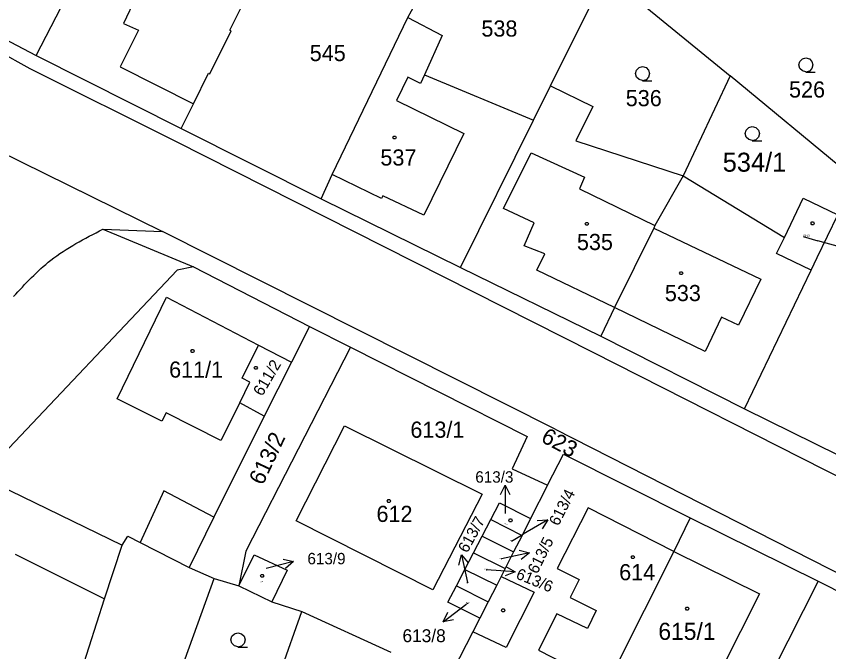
# Model space of a CAD drawing. Extents: x -621797 to -620972, y -1175539 to -1174697.
# Drawn here: x -621614.9 to -621529.4, y -1174912.8 to -1174845.9 of the extents above; entities that cross this region are included whole.
import ezdxf

# ---------------------------------------------------------------- set-up
doc = ezdxf.new("R2010")
doc.units = 0
for name, color, linetype in [('INZ mimo EON - nadz', 7, 'Continuous'), ('Rozvod plynu EON', 7, 'Continuous'), ('SDEL EON', 7, 'Continuous'), ('SDEL EON - popis', 7, 'Continuous'), ('Silnoproud EON', 7, 'Continuous'), ('Silnoproud EON - popis', 7, 'Continuous')]:
    doc.layers.add(name, color=color, linetype=linetype)

msp = doc.modelspace()

# ---------------------------------------------------------------- linework, layer by layer
at = {"layer": 'INZ mimo EON - nadz'}
for p, q in [((-621532.08, -1174869.11), (-621530.51, -1174869.55)), ((-621527.621, -1174870.36), (-621530.51, -1174869.55)), ((-621563.45, -1174895.28), (-621563.45, -1174898.28)), ((-621558.954, -1174898.939), (-621561.54, -1174900.46)), ((-621562.77, -1174901.18), (-621561.54, -1174900.46)), ((-621568.063, -1174902.62), (-621567.42, -1174905.55)), ((-621560.897, -1174902.42), (-621563.83, -1174903.05)), ((-621585.729, -1174903.343), (-621588.64, -1174904.07)), ((-621563.87, -1174903.06), (-621563.83, -1174903.05)), ((-621565.47, -1174904.2), (-621565.4, -1174904.21)), ((-621562.407, -1174904.418), (-621565.4, -1174904.21)), ((-621567.41, -1174905.6), (-621567.42, -1174905.55)), ((-621569.979, -1174909.672), (-621567.58, -1174907.87)), ((-621567.36, -1174907.71), (-621567.58, -1174907.87))]:
    msp.add_line(p, q, dxfattribs=at)
for points in [[(-621563.95, -1174896.28), (-621563.45, -1174895.28), (-621562.95, -1174896.28)], [(-621560.069, -1174899.015), (-621558.954, -1174898.939), (-621559.563, -1174899.877)], [(-621568.337, -1174903.704), (-621568.063, -1174902.62), (-621567.36, -1174903.489)], [(-621561.98, -1174902.141), (-621560.897, -1174902.42), (-621561.77, -1174903.119)], [(-621586.821, -1174903.101), (-621585.729, -1174903.343), (-621586.578, -1174904.071)], [(-621563.37, -1174903.85), (-621562.407, -1174904.418), (-621563.439, -1174904.847)], [(-621568.879, -1174909.471), (-621569.979, -1174909.672), (-621569.479, -1174908.671)]]:
    msp.add_lwpolyline(points, dxfattribs=at)
at = {"layer": 'Rozvod plynu EON'}
for points in [[(-621575.01, -1174858.53), (-621574.92, -1174858.68), (-621575.01, -1174858.83), (-621575.19, -1174858.83), (-621575.28, -1174858.68), (-621575.19, -1174858.53)], [(-621554.76, -1174867.62), (-621554.67, -1174867.77), (-621554.76, -1174867.92), (-621554.94, -1174867.92), (-621555.03, -1174867.77), (-621554.94, -1174867.62)], [(-621530.98, -1174867.56), (-621530.89, -1174867.71), (-621530.98, -1174867.86), (-621531.16, -1174867.86), (-621531.25, -1174867.71), (-621531.16, -1174867.56)], [(-621544.82, -1174872.82), (-621544.73, -1174872.97), (-621544.82, -1174873.12), (-621545, -1174873.12), (-621545.09, -1174872.97), (-621545, -1174872.82)], [(-621596.28, -1174881.02), (-621596.19, -1174881.17), (-621596.28, -1174881.32), (-621596.46, -1174881.32), (-621596.55, -1174881.17), (-621596.46, -1174881.02)], [(-621589.63, -1174882.79), (-621589.54, -1174882.94), (-621589.63, -1174883.09), (-621589.81, -1174883.09), (-621589.9, -1174882.94), (-621589.81, -1174882.79)], [(-621575.61, -1174896.82), (-621575.52, -1174896.97), (-621575.61, -1174897.12), (-621575.79, -1174897.12), (-621575.88, -1174896.97), (-621575.79, -1174896.82)], [(-621562.8, -1174898.84), (-621562.71, -1174898.99), (-621562.8, -1174899.14), (-621562.98, -1174899.14), (-621563.07, -1174898.99), (-621562.98, -1174898.84)], [(-621549.91, -1174902.73), (-621549.82, -1174902.88), (-621549.91, -1174903.03), (-621550.09, -1174903.03), (-621550.18, -1174902.88), (-621550.09, -1174902.73)], [(-621588.96, -1174904.7), (-621588.87, -1174904.85), (-621588.96, -1174905), (-621589.14, -1174905), (-621589.23, -1174904.85), (-621589.14, -1174904.7)], [(-621563.57, -1174908.33), (-621563.48, -1174908.48), (-621563.57, -1174908.63), (-621563.75, -1174908.63), (-621563.84, -1174908.48), (-621563.75, -1174908.33)], [(-621544.18, -1174908.15), (-621544.09, -1174908.3), (-621544.18, -1174908.45), (-621544.36, -1174908.45), (-621544.45, -1174908.3), (-621544.36, -1174908.15)]]:
    msp.add_lwpolyline(points, close=True, dxfattribs=at)
at = {"layer": 'SDEL EON'}
for points in [[(-621531.77, -1174851.77), (-621532.15, -1174851.67), (-621532.42, -1174851.4), (-621532.52, -1174851.03), (-621532.42, -1174850.66), (-621532.15, -1174850.39), (-621531.78, -1174850.29), (-621531.41, -1174850.39), (-621531.14, -1174850.66), (-621531.04, -1174851.04), (-621531.14, -1174851.42), (-621531.41, -1174851.69), (-621531.79, -1174851.79), (-621530.79, -1174851.79)], [(-621548.97, -1174852.68), (-621549.35, -1174852.58), (-621549.62, -1174852.31), (-621549.72, -1174851.94), (-621549.62, -1174851.57), (-621549.35, -1174851.3), (-621548.98, -1174851.2), (-621548.61, -1174851.3), (-621548.34, -1174851.57), (-621548.24, -1174851.95), (-621548.34, -1174852.33), (-621548.61, -1174852.6), (-621548.99, -1174852.7), (-621547.99, -1174852.7)], [(-621537.41, -1174859), (-621537.79, -1174858.9), (-621538.06, -1174858.63), (-621538.16, -1174858.26), (-621538.06, -1174857.89), (-621537.79, -1174857.62), (-621537.42, -1174857.52), (-621537.05, -1174857.62), (-621536.78, -1174857.89), (-621536.68, -1174858.27), (-621536.78, -1174858.65), (-621537.05, -1174858.92), (-621537.43, -1174859.02), (-621536.43, -1174859.02)], [(-621591.58, -1174912.32), (-621591.96, -1174912.22), (-621592.23, -1174911.95), (-621592.33, -1174911.58), (-621592.23, -1174911.21), (-621591.96, -1174910.94), (-621591.59, -1174910.84), (-621591.22, -1174910.94), (-621590.95, -1174911.21), (-621590.85, -1174911.59), (-621590.95, -1174911.97), (-621591.22, -1174912.24), (-621591.6, -1174912.34), (-621590.6, -1174912.34)]]:
    msp.add_lwpolyline(points, dxfattribs=at)
at = {"layer": 'SDEL EON - popis'}
for p, q in [((-621601.72, -1174842.63), (-621603.65, -1174846.67)), ((-621603.65, -1174846.67), (-621602.07, -1174847.39)), ((-621602.07, -1174847.39), (-621604, -1174851.25)), ((-621604, -1174851.25), (-621596.27, -1174855.13)), ((-621573.7, -1174852.34), (-621574.9, -1174854.77)), ((-621572.37, -1174852.98), (-621573.7, -1174852.34)), ((-621571.95, -1174852.07), (-621572.37, -1174852.98)), ((-621574.9, -1174854.77), (-621567.81, -1174858.27)), ((-621567.81, -1174858.27), (-621572.03, -1174866.85)), ((-621563.61, -1174866.15), (-621560.71, -1174860.3)), ((-621560.71, -1174860.3), (-621555.09, -1174862.87)), ((-621576.46, -1174865.1), (-621581.67, -1174862.56)), ((-621555.09, -1174862.87), (-621555.64, -1174864.1)), ((-621555.64, -1174864.1), (-621547.7, -1174867.96)), ((-621576.33, -1174864.83), (-621576.46, -1174865.1)), ((-621572.03, -1174866.85), (-621576.33, -1174864.83)), ((-621560.4, -1174867.68), (-621563.61, -1174866.15)), ((-621561.44, -1174870.07), (-621560.4, -1174867.68)), ((-621547.78, -1174868.23), (-621536.52, -1174873.61)), ((-621559.27, -1174870.93), (-621561.44, -1174870.07)), ((-621560.12, -1174872.66), (-621559.27, -1174870.93)), ((-621551.93, -1174876.6), (-621560.12, -1174872.66)), ((-621536.52, -1174873.61), (-621538.89, -1174878.45)), ((-621604.33, -1174886.21), (-621599.11, -1174875.51)), ((-621599.11, -1174875.51), (-621589.44, -1174880.54)), ((-621542.38, -1174881.22), (-621551.93, -1174876.6)), ((-621540.66, -1174877.61), (-621542.38, -1174881.22)), ((-621538.89, -1174878.45), (-621540.66, -1174877.61)), ((-621599.62, -1174888.57), (-621604.33, -1174886.21)), ((-621591.41, -1174886.63), (-621593.39, -1174890.59)), ((-621599.16, -1174887.66), (-621599.62, -1174888.57)), ((-621593.39, -1174890.59), (-621599.16, -1174887.66)), ((-621599.41, -1174895.88), (-621601.89, -1174901.33)), ((-621594.15, -1174898.65), (-621599.41, -1174895.88)), ((-621554.72, -1174897.69), (-621557.98, -1174904.06)), ((-621545.7, -1174902.28), (-621554.72, -1174897.69)), ((-621615.07, -1174902.56), (-621605.65, -1174907.25)), ((-621545.7, -1174902.28), (-621536.66, -1174906.74)), ((-621557.98, -1174904.06), (-621555.65, -1174905.22)), ((-621563.89, -1174904.92), (-621560.38, -1174906.56)), ((-621555.65, -1174905.22), (-621556.61, -1174907.12)), ((-621560.38, -1174906.56), (-621563.33, -1174912.38)), ((-621556.61, -1174907.12), (-621553.86, -1174908.51)), ((-621536.66, -1174906.74), (-621540.66, -1174914.68)), ((-621558.02, -1174908.83), (-621559.93, -1174912.69)), ((-621554.77, -1174910.4), (-621558.02, -1174908.83)), ((-621553.86, -1174908.51), (-621554.77, -1174910.4)), ((-621563.33, -1174912.38), (-621566.85, -1174910.73)), ((-621559.93, -1174912.69), (-621552.74, -1174916.32))]:
    msp.add_line(p, q, dxfattribs=at)
msp.add_spline([(-621615.24, -1174875.44), (-621611.31, -1174871.61), (-621605.82, -1174868.33)], degree=3, dxfattribs=at)
at = {"layer": 'Silnoproud EON'}
for p, q in [((-621612.85, -1174850.03), (-621607.58, -1174839.83)), ((-621573.72, -1174846.05), (-621571.06, -1174841.28)), ((-621558.66, -1174853.23), (-621552.83, -1174841.5)), ((-621552.83, -1174841.5), (-621539.76, -1174852.18)), ((-621592.44, -1174847.36), (-621590.22, -1174842.85)), ((-621627.87, -1174843.57), (-621613.5, -1174851.4)), ((-621619.93, -1174846.35), (-621612.85, -1174850.03)), ((-621581.67, -1174862.56), (-621573.72, -1174846.05)), ((-621573.72, -1174846.05), (-621570.07, -1174847.92)), ((-621594.55, -1174851.98), (-621592.3, -1174847.43)), ((-621592.3, -1174847.43), (-621592.44, -1174847.36)), ((-621570.07, -1174847.92), (-621571.95, -1174852.07)), ((-621612.85, -1174850.03), (-621597.57, -1174857.74)), ((-621613.5, -1174851.4), (-621598.19, -1174859.07)), ((-621596.27, -1174855.13), (-621594.68, -1174851.91)), ((-621594.68, -1174851.91), (-621594.55, -1174851.98)), ((-621571.95, -1174852.07), (-621560.45, -1174856.84)), ((-621539.76, -1174852.18), (-621544.71, -1174862.71)), ((-621526.62, -1174863.08), (-621539.76, -1174852.18)), ((-621560.45, -1174856.84), (-621558.66, -1174853.23)), ((-621558.66, -1174853.23), (-621554.23, -1174855.43)), ((-621597.57, -1174857.74), (-621596.27, -1174855.13)), ((-621554.23, -1174855.43), (-621556.02, -1174859.04)), ((-621568.17, -1174872.37), (-621560.45, -1174856.84)), ((-621597.57, -1174857.74), (-621582.84, -1174865.12)), ((-621598.19, -1174859.07), (-621554.21, -1174881.3)), ((-621556.02, -1174859.04), (-621544.71, -1174862.71)), ((-621617.77, -1174859.61), (-621599.53, -1174868.58)), ((-621582.84, -1174865.12), (-621581.67, -1174862.56)), ((-621544.71, -1174862.71), (-621547.7, -1174867.96)), ((-621544.71, -1174862.71), (-621534.04, -1174869.2)), ((-621582.84, -1174865.12), (-621568.17, -1174872.37)), ((-621534.04, -1174869.2), (-621532.05, -1174865.06)), ((-621532.05, -1174865.06), (-621528.42, -1174866.81)), ((-621530.58, -1174871.31), (-621528.42, -1174866.81)), ((-621605.82, -1174868.33), (-621596.28, -1174872.29)), ((-621605.82, -1174868.33), (-621599.53, -1174868.58)), ((-621558.17, -1174889.39), (-621599.53, -1174868.58)), ((-621547.78, -1174868.23), (-621551.93, -1174876.6)), ((-621547.7, -1174867.96), (-621547.78, -1174868.23)), ((-621534.86, -1174870.9), (-621534.04, -1174869.2)), ((-621531.23, -1174872.65), (-621534.86, -1174870.9)), ((-621531.23, -1174872.65), (-621530.58, -1174871.31)), ((-621597.99, -1174872.64), (-621618.6, -1174894.42)), ((-621596.28, -1174872.29), (-621597.99, -1174872.64)), ((-621596.28, -1174872.29), (-621584.06, -1174878.57)), ((-621568.17, -1174872.37), (-621553.38, -1174879.61)), ((-621538.25, -1174887.25), (-621531.23, -1174872.65)), ((-621551.93, -1174876.6), (-621553.38, -1174879.61)), ((-621584.06, -1174878.57), (-621585.96, -1174882.34)), ((-621584.06, -1174878.57), (-621579.74, -1174880.76)), ((-621553.38, -1174879.61), (-621538.25, -1174887.25)), ((-621591.15, -1174884.04), (-621589.44, -1174880.54)), ((-621589.44, -1174880.54), (-621585.96, -1174882.34)), ((-621579.74, -1174880.76), (-621590.75, -1174902.23)), ((-621579.74, -1174880.76), (-621561.12, -1174890.18)), ((-621554.21, -1174881.3), (-621509.01, -1174904.22)), ((-621585.96, -1174882.34), (-621588.82, -1174888.04)), ((-621591.41, -1174886.63), (-621590.33, -1174884.46)), ((-621590.33, -1174884.46), (-621591.15, -1174884.04)), ((-621588.82, -1174888.04), (-621591.41, -1174886.63)), ((-621538.25, -1174887.25), (-621528.33, -1174892.14)), ((-621588.82, -1174888.04), (-621594.15, -1174898.65)), ((-621585.46, -1174899.04), (-621580.39, -1174889.06)), ((-621580.39, -1174889.06), (-621565.89, -1174896.24)), ((-621558.17, -1174889.39), (-621511.97, -1174912.96)), ((-621561.12, -1174890.18), (-621562.71, -1174893.59)), ((-621558.98, -1174895.3), (-621557.32, -1174892.04)), ((-621557.32, -1174892.04), (-621543.95, -1174898.74)), ((-621562.71, -1174893.59), (-621558.98, -1174895.3)), ((-621618.6, -1174894.42), (-621603.78, -1174901.63)), ((-621558.98, -1174895.3), (-621560.77, -1174898.82)), ((-621565.89, -1174896.24), (-621571.06, -1174906.31)), ((-621564.96, -1174898.92), (-621564.05, -1174897.17)), ((-621564.05, -1174897.17), (-621560.77, -1174898.82)), ((-621594.15, -1174898.65), (-621596.74, -1174903.98)), ((-621571.06, -1174906.31), (-621585.46, -1174899.04)), ((-621565.87, -1174900.66), (-621564.96, -1174898.92)), ((-621564.96, -1174898.92), (-621561.67, -1174900.58)), ((-621560.77, -1174898.82), (-621561.67, -1174900.58)), ((-621543.95, -1174898.74), (-621545.7, -1174902.28)), ((-621543.95, -1174898.74), (-621530.48, -1174905.4)), ((-621603.78, -1174901.63), (-621603.2, -1174900.66)), ((-621603.2, -1174900.66), (-621601.89, -1174901.33)), ((-621566.78, -1174902.41), (-621565.87, -1174900.66)), ((-621565.87, -1174900.66), (-621562.56, -1174902.33)), ((-621561.67, -1174900.58), (-621562.56, -1174902.33)), ((-621605.65, -1174907.25), (-621603.78, -1174901.63)), ((-621601.89, -1174901.33), (-621596.74, -1174903.98)), ((-621590.75, -1174902.23), (-621591.49, -1174905.88)), ((-621591.49, -1174905.88), (-621589.88, -1174902.64)), ((-621589.88, -1174902.64), (-621586.42, -1174904.26)), ((-621567.69, -1174904.16), (-621566.78, -1174902.41)), ((-621566.78, -1174902.41), (-621563.46, -1174904.08)), ((-621562.56, -1174902.33), (-621563.46, -1174904.08)), ((-621545.7, -1174902.28), (-621551.93, -1174914.7)), ((-621596.74, -1174903.98), (-621594.11, -1174905.11)), ((-621586.42, -1174904.26), (-621588.03, -1174907.57)), ((-621568.59, -1174905.91), (-621567.69, -1174904.16)), ((-621567.69, -1174904.16), (-621564.34, -1174905.81)), ((-621563.46, -1174904.08), (-621563.89, -1174904.92)), ((-621598.4, -1174917), (-621594.11, -1174905.11)), ((-621594.11, -1174905.11), (-621591.49, -1174905.88)), ((-621563.89, -1174904.92), (-621564.34, -1174905.81)), ((-621530.48, -1174905.4), (-621537.24, -1174918.72)), ((-621530.48, -1174905.4), (-621525.16, -1174908.11)), ((-621591.49, -1174905.88), (-621588.03, -1174907.57)), ((-621569.48, -1174907.62), (-621568.59, -1174905.91)), ((-621568.59, -1174905.91), (-621565.24, -1174907.57)), ((-621564.34, -1174905.81), (-621565.24, -1174907.57)), ((-621608.32, -1174915.56), (-621605.65, -1174907.25)), ((-621588.03, -1174907.57), (-621584.88, -1174908.59)), ((-621566.13, -1174909.32), (-621569.48, -1174907.62)), ((-621565.24, -1174907.57), (-621566.13, -1174909.32)), ((-621588.97, -1174920.27), (-621584.88, -1174908.59)), ((-621584.88, -1174908.59), (-621575.51, -1174912.9)), ((-621566.13, -1174909.32), (-621566.85, -1174910.73)), ((-621566.85, -1174910.73), (-621569.41, -1174915.7))]:
    msp.add_line(p, q, dxfattribs=at)

# ---------------------------------------------------------------- texts
at = {"layer": 'INZ mimo EON - nadz'}
for s, height, p in [('613/3', 1.2, (-621566.598, -1174895.03)), ('613/9', 1.2, (-621584.278, -1174903.63)), ('613/8', 1.36, (-621574.264, -1174911.83))]:
    msp.add_text(s, height=height, dxfattribs=at).set_placement(p)
for s, rotation, p in [('613/4', 62.96806, (-621557.849, -1174899.668)), ('613/7', 61.1346, (-621567.448, -1174902.51)), ('613/5', 63.7702, (-621560.076, -1174904.721)), ('613/6', 337.58673, (-621562.403, -1174905.093))]:
    msp.add_text(s, height=1.19, rotation=rotation, dxfattribs=at).set_placement(p)
at = {"layer": 'Silnoproud EON - popis'}
for s, height, p in [('538', 1.7, (-621565.953, -1174848.05)), ('545', 1.7, (-621584.033, -1174850.63)), ('526', 1.7, (-621533.553, -1174854.47)), ('536', 1.7, (-621550.753, -1174855.38)), ('537', 1.7, (-621576.593, -1174861.63)), ('534/1', 2, (-621540.537, -1174862.28)), ('535', 1.7, (-621555.893, -1174870.53)), ('534/2', 0.2, (-621532.052, -1174869.11)), ('533', 1.7, (-621546.633, -1174875.91)), ('611/1', 1.7, (-621598.843, -1174883.97)), ('613/1', 1.7, (-621573.433, -1174890.3)), ('612', 1.7, (-621577.003, -1174899.17)), ('613/4', 0.1, (-621562.957, -1174901.18)), ('613/5', 0.1, (-621564.059, -1174903.06)), ('614', 1.7, (-621551.443, -1174905.31)), ('613/6', 0.1, (-621565.657, -1174904.2)), ('613/7', 0.1, (-621567.594, -1174905.6)), ('613/8', 0.1, (-621567.548, -1174907.71)), ('615/1', 1.8, (-621547.318, -1174911.59))]:
    msp.add_text(s, height=height, dxfattribs=at).set_placement(p)
for s, height, rotation, p in [('611/2', 1.2, 59.41572, (-621589.042, -1174886.003)), ('613/2', 1.7, 64.80153, (-621588.978, -1174895.387)), ('623', 1.7, 332.08634, (-621559.785, -1174890.667)), ('613/3', 0.1, 333.9198, (-621563.521, -1174899.359)), ('613/9', 0.1, 12.60507, (-621589.24, -1174905.535))]:
    msp.add_text(s, height=height, rotation=rotation, dxfattribs=at).set_placement(p)

doc.saveas('drawing.dxf')
